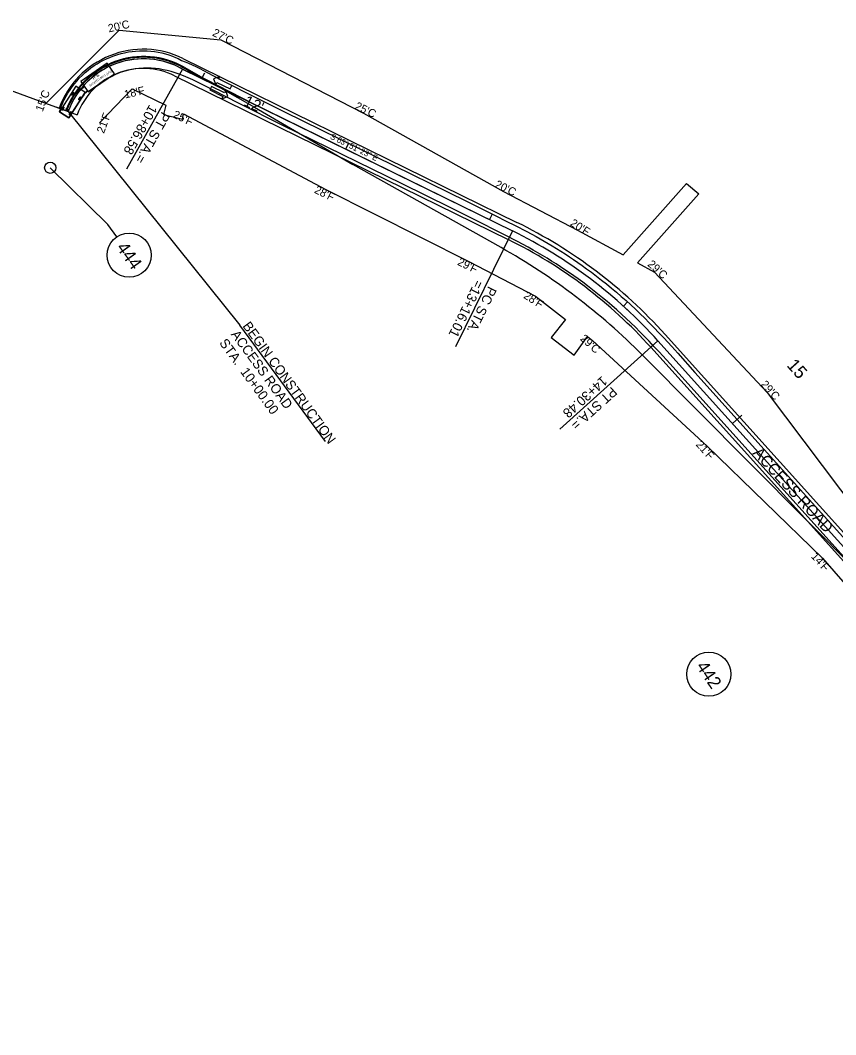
# Model space of a CAD drawing. Extents: x 1968740 to 1970715, y 796044 to 797557.
# Drawn here: x 1969442 to 1969951, y 796924 to 797557 of the extents above; entities that cross this region are included whole.
import ezdxf

# ---------------------------------------------------------------- set-up
doc = ezdxf.new("R2010")
doc.units = 0
for name, color, linetype in [('RD_EX_DV_TX_Prop', 7, 'Continuous'), ('RD_HC_CL_Rel', 7, 'Continuous'), ('RD_HC_Data_Rel', 7, 'Continuous'), ('RD_PD_ALT3_CL', 7, 'Continuous'), ('RD_PD_ALT4_CL', 7, 'Continuous'), ('RD_PD_ALT5_CL', 7, 'Continuous'), ('RD_PD_CstnLmt', 7, 'Continuous'), ('RD_PD_CstnLmt_TX', 7, 'Continuous'), ('RD_PD_Final_TrvlWay', 7, 'Continuous'), ('RD_PD_Final_TX', 7, 'Continuous'), ('RD_SHT_TX', 7, 'Continuous')]:
    doc.layers.add(name, color=color, linetype=linetype)

msp = doc.modelspace()

# ---------------------------------------------------------------- linework, layer by layer
at = {"layer": 'RD_EX_DV_TX_Prop'}
msp.add_lwpolyline([(1969502.46, 797421.94), (1969496.83, 797429.58), (1969460.79, 797464.99)], dxfattribs=at)
for centre, radius in [((1969460.79, 797464.99), 3.5), ((1969510.06, 797410.4), 13.75), ((1969871.88, 797148.7), 13.75)]:
    msp.add_circle(centre, radius, dxfattribs=at)
at = {"layer": 'RD_HC_CL_Rel'}
for p, q in [((1969543.42, 797526.6), (1969749.37, 797425.51)), ((1969840.13, 797356.88), (1970142.43, 797020.84))]:
    msp.add_line(p, q, dxfattribs=at)
for centre, radius, start, end in [((1969518.96, 797482.99), 50, 60.71699, 159.92961), ((1969617.1, 797156.24), 300, 41.97435, 63.83785)]:
    msp.add_arc(centre, radius, start, end, dxfattribs=at)
at = {"layer": 'RD_HC_Data_Rel'}
for p, q in [((1969390.42, 797529.95), (1969472, 797500.15)), ((1969543.42, 797526.6), (1969508.35, 797464.06)), ((1969555.47, 797520.68), (1969557.23, 797524.27)), ((1969472, 797500.15), (1969464.48, 797502.89)), ((1969645.24, 797476.62), (1969647, 797480.21)), ((1969735, 797432.56), (1969736.77, 797436.15)), ((1969749.37, 797425.51), (1969713.82, 797353.13)), ((1969818.63, 797378.47), (1969821.32, 797381.43)), ((1969818.63, 797378.47), (1969822.31, 797375.08)), ((1969840.13, 797356.88), (1969778.88, 797301.78)), ((1969886.63, 797305.2), (1969892.57, 797310.55))]:
    msp.add_line(p, q, dxfattribs=at)
at = {"layer": 'RD_PD_ALT3_CL'}
for p, q in [((1969541.01, 797527.86), (1969749.37, 797425.51)), ((1969840.13, 797356.88), (1970142.43, 797020.84))]:
    msp.add_line(p, q, dxfattribs=at)
for centre, radius, start, end in [((1969518.96, 797482.99), 50, 63.83785, 159.92961), ((1969617.1, 797156.24), 300, 41.97435, 63.83785)]:
    msp.add_arc(centre, radius, start, end, dxfattribs=at)
at = {"layer": 'RD_PD_ALT4_CL'}
for p, q in [((1969544.44, 797527.74), (1969588.24, 797502.81)), ((1969588.24, 797502.81), (1969649.59, 797467.06)), ((1969742.22, 797415.11), (1969649.59, 797467.06)), ((1970251.76, 796923.56), (1969830.46, 797348.01))]:
    msp.add_line(p, q, dxfattribs=at)
for centre, radius, start, end in [((1969518.96, 797482.99), 51.5, 60.34376, 159.92961), ((1969546.57, 797066.23), 400, 44.7863, 60.71699)]:
    msp.add_arc(centre, radius, start, end, dxfattribs=at)
at = {"layer": 'RD_PD_ALT5_CL'}
for p, q in [((1969496.41, 797530.26), (1969479.92, 797518.95)), ((1969500.94, 797523.66), (1969496.41, 797530.26)), ((1969542.32, 797528.32), (1969588.15, 797504.7)), ((1969484.44, 797512.35), (1969500.94, 797523.66)), ((1969489.03, 797525.04), (1969490.75, 797526.21)), ((1969489.1, 797524.93), (1969490.82, 797526.11)), ((1969489.18, 797524.82), (1969490.89, 797526)), ((1969476.76, 797515.84), (1969466.49, 797499.86)), ((1969482.65, 797512.06), (1969476.76, 797515.84)), ((1969479.7, 797513.95), (1969482.18, 797515.65)), ((1969479.92, 797518.95), (1969484.44, 797512.35)), ((1969493.26, 797518.87), (1969494.98, 797520.05)), ((1969493.33, 797518.76), (1969495.05, 797519.94)), ((1969493.41, 797518.65), (1969495.12, 797519.83)), ((1969472.38, 797496.07), (1969482.65, 797512.06)), ((1969474.03, 797510.42), (1969475.15, 797512.17)), ((1969474.14, 797510.35), (1969475.26, 797512.1)), ((1969474.24, 797510.28), (1969475.37, 797512.03)), ((1969478.64, 797507.46), (1969479.76, 797509.21)), ((1969478.75, 797507.39), (1969479.87, 797509.14)), ((1969478.86, 797507.32), (1969479.98, 797509.07)), ((1969484.44, 797512.35), (1969484.44, 797512.35)), ((1969468.24, 797500.99), (1969468.98, 797502.94)), ((1969468.36, 797500.95), (1969469.1, 797502.89)), ((1969468.48, 797500.9), (1969469.22, 797502.85)), ((1969588.15, 797504.7), (1969749.37, 797425.51)), ((1969466.49, 797499.86), (1969472.38, 797496.07)), ((1969472.92, 797498.12), (1969473.61, 797500.09)), ((1969473.04, 797498.08), (1969473.74, 797500.04)), ((1969473.17, 797498.04), (1969473.86, 797500)), ((1969472.38, 797496.07), (1969472.38, 797496.07)), ((1969840.13, 797356.88), (1970142.43, 797020.84))]:
    msp.add_line(p, q, dxfattribs=at)
for points in [[(1970109.56, 797051.43), (1969847.75, 797342.43), (1969840.81, 797350.05), (1969837.64, 797353.46), (1969834.66, 797356.59), (1969831.66, 797359.7), (1969828.86, 797362.54), (1969826.03, 797365.35), (1969823.17, 797368.12), (1969820.27, 797370.86), (1969817.34, 797373.57), (1969814.38, 797376.25), (1969811.38, 797378.88), (1969808.35, 797381.48), (1969805.54, 797383.82), (1969802.45, 797386.34), (1969799.32, 797388.82), (1969796.16, 797391.26), (1969793.24, 797393.45), (1969790.29, 797395.61), (1969787.58, 797397.55), (1969784.85, 797399.45), (1969782.11, 797401.32), (1969779.34, 797403.16), (1969776.55, 797404.97), (1969773.74, 797406.75), (1969770.91, 797408.5), (1969768.06, 797410.21), (1969765.19, 797411.89), (1969762.3, 797413.54), (1969759.11, 797415.32), (1969752.39, 797418.96), (1969744.72, 797422.97), (1969738.21, 797426.3), (1969730.78, 797430.04), (1969710.93, 797439.9), (1969680.14, 797455.06), (1969615.87, 797486.63), (1969606.4, 797491.26), (1969596.06, 797496.36), (1969588.69, 797500.06), (1969579.57, 797504.69), (1969569.3, 797509.94), (1969557.26, 797516.14), (1969554.3, 797517.69), (1969553.12, 797518.28), (1969549.83, 797519.86), (1969546.82, 797521.22), (1969544.09, 797522.36), (1969541.33, 797523.41), (1969538.85, 797524.26), (1969536.35, 797525.02), (1969533.82, 797525.67), (1969531.27, 797526.23), (1969528.7, 797526.66), (1969526.44, 797526.95), (1969523.85, 797527.16), (1969521.57, 797527.24), (1969520.27, 797527.24), (1969518.96, 797527.21), (1969516.69, 797527.06), (1969514.32, 797526.8), (1969511.96, 797526.43), (1969509.63, 797525.93), (1969507.33, 797525.32), (1969505.06, 797524.59), (1969503.39, 797523.96), (1969501.19, 797523.03), (1969499.58, 797522.25), (1969498, 797521.41), (1969496.46, 797520.51), (1969494.46, 797519.22), (1969484.5, 797512.39), (1969483.63, 797512.85), (1969482.82, 797511.87), (1969482.04, 797510.86), (1969481.28, 797509.83), (1969480.55, 797508.78), (1969472.38, 797496.07), (1969466.49, 797499.86), (1969467.32, 797502.24), (1969467.84, 797503.57), (1969468.39, 797504.89), (1969468.97, 797506.19), (1969469.59, 797507.48), (1969470.76, 797509.7), (1969471.83, 797511.56), (1969473.18, 797513.67), (1969474.41, 797515.42), (1969475.92, 797517.41), (1969477.53, 797519.33), (1969478.97, 797520.91), (1969480.73, 797522.68), (1969482.57, 797524.37), (1969484.48, 797525.98), (1969486.18, 797527.29), (1969488.25, 797528.75), (1969490.12, 797529.95), (1969492.04, 797531.07), (1969494, 797532.12), (1969496, 797533.08), (1969498.38, 797534.1), (1969500.46, 797534.89), (1969502.91, 797535.7), (1969505.05, 797536.29), (1969507.2, 797536.81), (1969509.73, 797537.29), (1969511.92, 797537.61), (1969514.12, 797537.84), (1969516.62, 797538), (1969518.95, 797538.04), (1969521.29, 797537.97), (1969523.62, 797537.81), (1969525.95, 797537.54), (1969528.27, 797537.16), (1969530.57, 797536.68), (1969532.86, 797536.09), (1969534.81, 797535.49), (1969537.07, 797534.69), (1969538.98, 797533.89), (1969540.57, 797533.15), (1969542.77, 797532.04), (1969544.96, 797531.17), (1969547.12, 797530.24), (1969551.72, 797528.14), (1969554.14, 797526.97), (1969556.56, 797525.76), (1969559.27, 797524.35), (1969569.74, 797518.73), (1969587.42, 797509.71), (1969601.25, 797502.75), (1969606.98, 797499.91), (1969720.54, 797444.1), (1969738.86, 797435.02), (1969745.43, 797431.72), (1969751.09, 797428.85), (1969758.2, 797425.15), (1969764.08, 797421.99), (1969769.03, 797419.2), (1969774.2, 797416.14), (1969776.77, 797414.57), (1969779.6, 797412.8), (1969782.13, 797411.18), (1969784.92, 797409.35), (1969787.42, 797407.68), (1969790.17, 797405.79), (1969792.91, 797403.87), (1969795.62, 797401.93), (1969798.58, 797399.75), (1969801.77, 797397.34), (1969804.94, 797394.88), (1969808.07, 797392.39), (1969811.17, 797389.85), (1969814.24, 797387.27), (1969817.27, 797384.66), (1969820.27, 797382), (1969823.24, 797379.31), (1969826.17, 797376.58), (1969829.06, 797373.82), (1969831.93, 797371.02), (1969834.76, 797368.19), (1969837.79, 797365.08), (1969840.78, 797361.94), (1969843.75, 797358.77), (1969848.72, 797353.35), (1969852.53, 797349.14), (1969863.24, 797337.18), (1970079.53, 797096.75)], [(1969471.06, 797500.49), (1969472.33, 797501.29), (1969471.32, 797501.19), (1969470.61, 797501.92), (1969471.06, 797500.49)]]:
    msp.add_lwpolyline(points, dxfattribs=at)
for points in [[(1969489.19, 797524.8), (1969489.01, 797525.06), (1969489.2, 797525.31), (1969490.43, 797526.16), (1969490.73, 797526.24), (1969490.91, 797525.97), (1969490.73, 797525.73), (1969489.49, 797524.88)], [(1969493.42, 797518.63), (1969493.24, 797518.89), (1969493.43, 797519.14), (1969494.66, 797519.99), (1969494.96, 797520.07), (1969495.14, 797519.8), (1969494.96, 797519.56), (1969493.72, 797518.71)], [(1969474.27, 797510.26), (1969474, 797510.44), (1969474.07, 797510.73), (1969474.88, 797512), (1969475.12, 797512.19), (1969475.4, 797512.01), (1969475.32, 797511.72), (1969474.51, 797510.45)], [(1969478.88, 797507.3), (1969478.61, 797507.48), (1969478.68, 797507.77), (1969479.49, 797509.04), (1969479.73, 797509.23), (1969480.01, 797509.05), (1969479.93, 797508.75), (1969479.12, 797507.49)], [(1969468.51, 797500.89), (1969468.21, 797501), (1969468.22, 797501.31), (1969468.75, 797502.71), (1969468.95, 797502.95), (1969469.25, 797502.84), (1969469.24, 797502.53), (1969468.71, 797501.13)], [(1969471.06, 797500.49), (1969472.33, 797501.29), (1969471.32, 797501.19), (1969470.61, 797501.92)], [(1969473.2, 797498.03), (1969472.89, 797498.13), (1969472.9, 797498.44), (1969473.39, 797499.86), (1969473.58, 797500.1), (1969473.89, 797499.99), (1969473.89, 797499.68), (1969473.39, 797498.27)]]:
    msp.add_lwpolyline(points, close=True, dxfattribs=at)
for centre, radius in [((1969542.32, 797528.32), 0.0417), ((1969542.32, 797528.32), 0.0417), ((1969479.7, 797513.95), 0.533), ((1969588.15, 797504.7), 0.0417), ((1969588.15, 797504.7), 0.0417), ((1969471.06, 797500.49), 0.0417), ((1969749.37, 797425.51), 0.0417), ((1969749.37, 797425.51), 0.0417), ((1969840.13, 797356.88), 0.0417), ((1969840.13, 797356.88), 0.0417)]:
    msp.add_circle(centre, radius, dxfattribs=at)
for centre, radius, start, end in [((1969518.96, 797482.99), 51, 62.73689, 159.92961), ((1969617.1, 797156.24), 300, 41.97435, 63.83785)]:
    msp.add_arc(centre, radius, start, end, dxfattribs=at)
at = {"layer": 'RD_PD_CstnLmt'}
for p, q in [((1969458.12, 797505.21), (1969503.74, 797550.9)), ((1969503.74, 797550.9), (1969567.34, 797544.88)), ((1969567.34, 797544.88), (1969656.27, 797499.1)), ((1969491.52, 797493.01), (1969511.93, 797514.35)), ((1969511.93, 797514.35), (1969533.02, 797504.07)), ((1969533.02, 797504.07), (1969531.61, 797498.16)), ((1969531.61, 797498.16), (1969543.28, 797495.36)), ((1969543.28, 797495.36), (1969544.08, 797498.7)), ((1969544.08, 797498.7), (1969632.85, 797451.38)), ((1969656.27, 797499.1), (1969743.67, 797450.21)), ((1969818.35, 797410.56), (1969858.07, 797455.17)), ((1969858.07, 797455.17), (1969865.75, 797448.76)), ((1969632.85, 797451.38), (1969722.16, 797406.4)), ((1969743.67, 797450.21), (1969789.98, 797426)), ((1969865.75, 797448.76), (1969827.37, 797405.65)), ((1969789.98, 797426), (1969818.35, 797410.56)), ((1969722.16, 797406.4), (1969763.62, 797384.87)), ((1969827.37, 797405.65), (1969838.02, 797399.85)), ((1969838.02, 797399.85), (1969908.25, 797324.65)), ((1969763.62, 797384.87), (1969782.54, 797370.17)), ((1969782.54, 797370.17), (1969773.45, 797358.91)), ((1969773.45, 797358.91), (1969787.87, 797347.92)), ((1969787.87, 797347.92), (1969796.11, 797359.62)), ((1969796.11, 797359.62), (1969799.29, 797357.15)), ((1969799.29, 797357.15), (1969870.92, 797291.07)), ((1969908.25, 797324.65), (1969968.59, 797244.43)), ((1969870.92, 797291.07), (1969942.82, 797221.25)), ((1969942.82, 797221.25), (1970008.45, 797145.77))]:
    msp.add_line(p, q, dxfattribs=at)
at = {"layer": 'RD_PD_Final_TrvlWay'}
for p, q in [((1969543.65, 797533.25), (1969752.02, 797430.89)), ((1969538.36, 797522.48), (1969746.73, 797420.12)), ((1969466.36, 797502.2), (1969477.63, 797498.09)), ((1969844.59, 797360.89), (1970146.89, 797024.85)), ((1969835.67, 797352.87), (1970137.97, 797016.83))]:
    msp.add_line(p, q, dxfattribs=at)
for centre, radius, start, end in [((1969518.96, 797482.99), 56, 63.83785, 159.92961), ((1969518.96, 797482.99), 44, 63.83785, 159.92961), ((1969617.1, 797156.24), 306, 41.97435, 63.83785), ((1969617.1, 797156.24), 294, 41.97435, 63.83785)]:
    msp.add_arc(centre, radius, start, end, dxfattribs=at)
at = {"layer": 'RD_PD_Final_TX'}
for p in [(1969472, 797500.15), (1969632.63, 797293.99)]:
    msp.add_line(p, (1969579.11, 797366.59), dxfattribs=at)
at = {"layer": 'RD_SHT_TX'}
for points in [[(1969573.07, 797514.26), (1969574.12, 797516.42), (1969565.88, 797520.44), (1969566.6, 797521.91), (1969562.81, 797520.61), (1969564.11, 797516.82), (1969564.83, 797518.29)], [(1969561.39, 797515.76), (1969560.34, 797513.6), (1969568.58, 797509.58), (1969567.86, 797508.11), (1969571.64, 797509.41), (1969570.34, 797513.2), (1969569.63, 797511.73)]]:
    msp.add_lwpolyline(points, close=True, dxfattribs=at)

# ---------------------------------------------------------------- texts
at = {"layer": 'RD_EX_DV_TX_Prop'}
for s, rotation, p in [('444', 305.55613, (1969501.79, 797415.09)), ('442', 304.22238, (1969863.72, 797153.58))]:
    msp.add_text(s, height=8, rotation=rotation, dxfattribs=at).set_placement(p)
at = {"layer": 'RD_HC_Data_Rel'}
for s, height, rotation, p in [('10+86.58', 6, 240.71699, (1969522.76, 797504.79)), ('PT STA.= ', 6, 240.71699, (1969530.61, 797500.39)), ('S 63%%d 51\' 23" E', 3.6, 333.85637, (1969635.19, 797483.27)), ('=13+16.01', 6, 243.83785, (1969726.26, 797395.4)), ('PC STA.', 6, 243.83785, (1969734.34, 797391.43)), ('15', 8, 311.97435, (1969920.14, 797341.28)), ('14+30.48', 6, 221.97435, (1969805.25, 797335.23)), ('PT STA.=', 6, 221.97435, (1969811.27, 797328.54))]:
    msp.add_text(s, height=height, rotation=rotation, dxfattribs=at).set_placement(p)
at = {"layer": 'RD_PD_ALT5_CL'}
for s, height, p in [('AASHTO 2011 (US)', 1.3333, (1969485.69, 797515.62)), ('P-B', 2, (1969487.94, 797519.79)), ('(c) 2021 Transoft Solutions, Inc. All rights reserved.', 0.08, (1969489.1, 797520.35))]:
    msp.add_text(s, height=height, rotation=34.43625, dxfattribs=at).set_placement(p)
at = {"layer": 'RD_PD_CstnLmt_TX'}
for s, rotation, p in [("20'C", 12.63388, (1969497.49, 797549.5)), ("27'C", 333.85637, (1969561.59, 797547.7)), ("18'F", 12.63388, (1969507.61, 797508.25)), ("15'C", 69.92961, (1969456.09, 797499.65)), ("25'C", 333.85637, (1969650.52, 797501.92)), ("21'F", 69.92961, (1969494.31, 797486.09)), ("25'F", 333.85637, (1969536.93, 797496.61)), ("28'F", 333.85637, (1969625.23, 797449.55)), ("20'C", 333.85637, (1969737.92, 797453.04)), ("20'F", 327.34563, (1969784.9, 797429.26)), ("29'F", 333.85637, (1969714.55, 797404.56)), ("29'C", 317.79633, (1969833.28, 797404.16)), ("28'F", 327.34563, (1969755.84, 797383.91)), ("29'C", 317.79633, (1969791.19, 797357.75)), ("29'C", 311.97435, (1969903.97, 797329.41)), ("21'F", 311.97435, (1969863.49, 797291.85)), ("14'F", 311.97435, (1969935.39, 797222.03))]:
    msp.add_text(s, height=5, rotation=rotation, dxfattribs=at).set_placement(p)
at = {"layer": 'RD_PD_Final_TX'}
for s, p in [('BEGIN CONSTRUCTION', (1969580.6, 797366.14)), ('STA.  10+00.00', (1969566.05, 797355.55)), ('ACCESS ROAD', (1969573.33, 797360.85))]:
    msp.add_text(s, height=5.9996, rotation=306.06576, dxfattribs=at).set_placement(p)
at = {"layer": 'RD_SHT_TX'}
for s, rotation, p in [("12'", 334.94659, (1969580.95, 797504.17)), ('ACCESS ROAD', 312.59078, (1969898.93, 797286.51))]:
    msp.add_text(s, height=7, rotation=rotation, dxfattribs=at).set_placement(p)

doc.saveas('drawing.dxf')
